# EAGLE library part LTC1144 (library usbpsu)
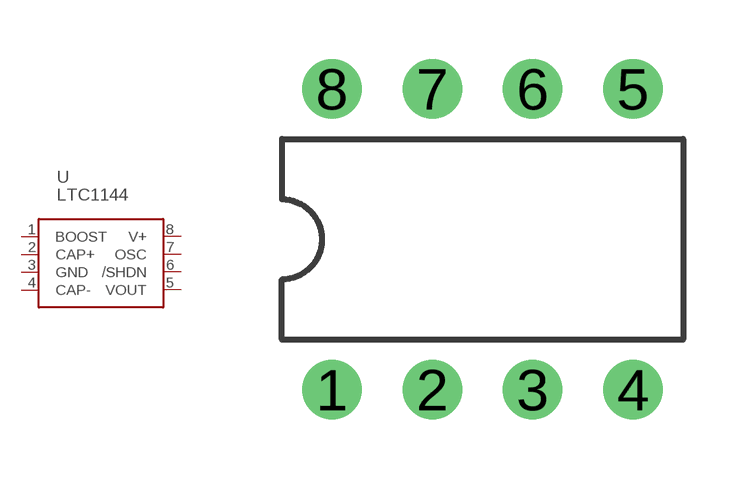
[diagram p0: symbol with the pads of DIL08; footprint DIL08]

Designator prefix -

## LTC1144CN8  [DIL08]
1  BOOST  in
2  CAP+  pas
3  GND  pwr
4  CAP-  pas
5  VOUT  out
6  /SHDN  in
7  OSC  in
8  V+  pwr

## Footprint DIL08 (pad centres in mm)
Dual In Line
drill 1 round: 1 -3.81,-3.81; 2 -1.27,-3.81; 3 1.27,-3.81; 4 3.81,-3.81; 5 3.81,3.81; 6 1.27,3.81; 7 -1.27,3.81; 8 -3.81,3.81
